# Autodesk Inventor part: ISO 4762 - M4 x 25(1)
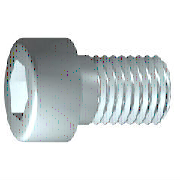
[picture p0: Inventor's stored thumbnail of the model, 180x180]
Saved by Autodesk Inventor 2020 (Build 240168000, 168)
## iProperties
Created: 2019-01
Part Number: ISO 4762 - M4 x 25(1)
Material: Nerezová ocel 440C
Description: Šroub s válcovou hlavou s vnitřním šestihranem
Document SubType Name: Modeling
Standard: ISO 4762
Designer: doma
Standard Revision: Fourth edition 2004-03-01
Standards Organization: ISO
Language: cs-CZ
Size Designation: M4 x 25
Categories: <MemberInstance><Categories><Category DisplayName="Spojovací materiál" InternalName="e4da775c-781d-43d5-af7c-5136215cf5a6" Mnemonic="FSTN"><Category DisplayName
Density: 7.75 g/cm^3
Appearance: Pololeštěná
IsCustomPart: 0
Author: doma
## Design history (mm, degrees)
sketch "Náčrt1"
  geometry: L1 (-1, 0)-(25, 0); L2 (25, 0)-(25, 2); L3 (25, 2)-(1.75, 2); L4 (1.75, 2)-(1.32, 2); L5 (1.32, 2)-(0, 2); L6 (0, 2)-(0, 3.5); L7 (0, 3.5)-(-4, 3.5); L8 (-4, 3.5)-(-4, 1.732); L9 (-4, 1.732)-(-2, 1.732); L10 (-2, 1.732)-(-1, 0); L11 (-9.8, 0)-(30.8, 0) reference; L12 (0, -0.7)-(0, 4.2) reference; L13 (1.75, 2)-(0, 2)
  constraints: 22 end point, 6 parallel, 2 collinear, 2 perpendicular, 1 horizontal, 1 point on line
  dimensions: "d1" = 23.25 distance from line of L3.end L2 (= GEL); "d2" = 0.42952 distance of L4.end L3.end (computed from GAL); "d3" = 4 distance between parallel lines of L8 L6 (= KOH); "d4" = 2 distance of L8.end L9.end (= INTI); "d5" = 60 deg angle of L10 L1; "d6" = 4 diameter of L3 L1 (= GD); "d7" = 4 diameter of L5 L1 (= BDM); "d8" = 3.4641 diameter of L9 L1 (= 1.1547 x SW); "d9" = 7 diameter of L7 L1 (= KOD); "d26" = 25 distance between parallel lines of L12 L2 (= NLG)
revolve "Těleso" sketch "Náčrt1" stored, may be unused: angle "d10" = 90 deg
sketch "Náčrt2"
  geometry: L1 (0, -4.9)-(0, 4.9) reference; L2 (-4.9, 0)-(4.9, 0) reference; L3 (1.732, 0)-(0.866, -1.5); L4 (0.866, -1.5)-(-0.866, -1.5); L5 (-0.866, -1.5)-(-1.732, 0); L6 (-1.732, 0)-(-0.866, 1.5); L7 (-0.866, 1.5)-(0.866, 1.5); L8 (0.866, 1.5)-(1.732, 0); 2 further points
  constraints: 12 end point, 1 coincident, 1 horizontal alignment, 1 point on line, 12 other
extrude "Drážka" join sketch "Náčrt2" stored distance "d11" = 10; taper "d12" = 0 deg
workplane "Work Plane1"
fillet "Fillet2" dims "d30" = 0.1 (= R)
body "Solid1"
fillet "Zaoblení1" dims "d17" = 0.4 (= RR)
feature "Závit" dims "d13" = 23.25 (= GEL), "d14" = 0
chamfer "Zkosení1" distance "d15" = 0.42941 (= -0.5 x SPD + 0.5 x GD); stored, may be unused: second distance "d16" = 0.42941 (= GUL), angle "d27" = 45 deg
other parameters: "GD" = 4 [user parameter; used in 2 equation terms], "NLG" = 25 [user parameter; used in 1 equation term], "GEL" = 23.25 [user parameter; used in 2 equation terms], "KOD" = 7 [user parameter; used in 1 equation term], "KOH" = 4 [user parameter; used in 1 equation term], "INTI" = 2 [user parameter; used in 1 equation term], "GAL" = 0.42941 (= 0.61345 x PTC) [user parameter; used in 1 equation term], "GUL" = 0.42941 (= 0.61345 x PTC) [user parameter; used in 1 equation term], "BDM" = 4 (= NND) [user parameter; used in 1 equation term], "SW" = 3 [user parameter; used in 2 equation terms], "RR" = 0.4 [user parameter; used in 1 equation term], "SPD" = 3.14117 (= NND - 1.2269 x PTC) [user parameter; used in 1 equation term], "d19" = 0, "d28" = 0, "d29" = 0, "R" = 0.1 [user parameter; used in 1 equation term], "TOA" = 30 deg [user parameter], "GD1" = 3.14117 (= THREADDIA - 1.2269 x PTC) [user parameter], "THREADDIA" = 4 [user parameter; used in 1 equation term], "FAWI" = 45 deg [user parameter], "TPU" = 14.28571 (computed from PTC) [user parameter], "PTC" = 0.7 [user parameter; used in 5 equation terms], "NND" = 4 [user parameter; used in 2 equation terms], "E0" = 3.465 (= 1.155 x SW) [user parameter]
